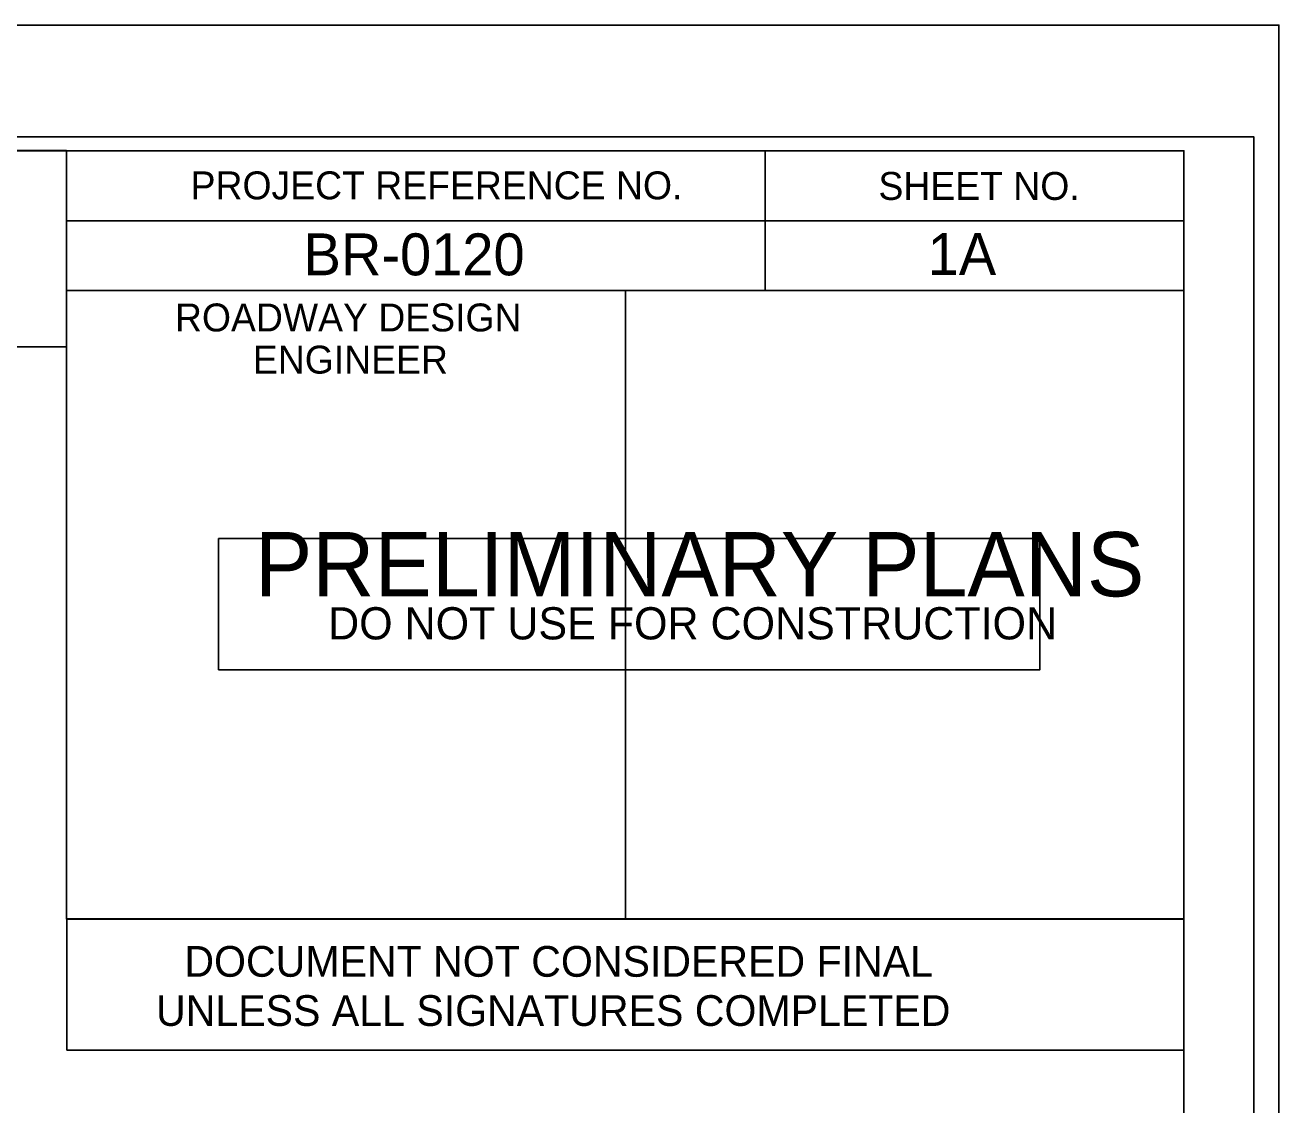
# Model space of a CAD drawing. Extents: x 2486563 to 2488026, y 371425 to 372193.
# Drawn here: x 2487379.5 to 2487469.3, y 372067.8 to 372145.1 of the extents above; entities that cross this region are included whole.
import ezdxf

# ---------------------------------------------------------------- set-up
doc = ezdxf.new("R2010")
doc.units = 0
for name, color, linetype in [('Sheet Block Title CELL', 7, 'Continuous'), ('Sheet Cutting Line CELL', 7, 'Continuous'), ('Sheet Data Field CELL', 7, 'Continuous'), ('Sheet Plan CELL', 7, 'Continuous'), ('Sheet Plot Border Inside CELL', 7, 'Continuous'), ('Sheet Plot Border Outside CELL', 7, 'Continuous'), ('Sheet Sticker Exception Certification CELL', 7, 'Continuous'), ('Sheet Sticker Preliminary CELL', 7, 'Continuous'), ('Sheet Typical CELL', 7, 'Continuous')]:
    doc.layers.add(name, color=color, linetype=linetype)

msp = doc.modelspace()

# ---------------------------------------------------------------- linework, layer by layer
at = {"layer": 'Sheet Block Title CELL'}
msp.add_lwpolyline([(2487382.471, 372126.093), (2487422.491, 372126.093), (2487422.491, 372081.093), (2487382.471, 372081.093)], close=True, dxfattribs=at)
at = {"layer": 'Sheet Cutting Line CELL'}
msp.add_line((2487469.291, 372145.113), (2486795.891, 372145.113), dxfattribs=at)
at = {"layer": 'Sheet Plan CELL'}
for p, q in [((2487432.491, 372136.093), (2487432.491, 372126.093)), ((2487382.471, 372131.093), (2487462.491, 372131.093)), ((2487382.471, 372126.093), (2487462.491, 372126.093)), ((2487382.471, 372126.093), (2487462.491, 372126.093)), ((2487422.491, 372126.093), (2487422.491, 372081.113))]:
    msp.add_line(p, q, dxfattribs=at)
for points in [[(2487462.491, 372136.113), (2486862.491, 372136.113), (2486862.491, 371716.113), (2487462.491, 371716.113)], [(2487382.471, 372136.113), (2487462.491, 372136.113), (2487462.491, 372126.093), (2487382.471, 372126.093)], [(2487422.491, 372126.093), (2487462.491, 372126.093), (2487462.491, 372081.093), (2487422.491, 372081.093)]]:
    msp.add_lwpolyline(points, close=True, dxfattribs=at)
at = {"layer": 'Sheet Plot Border Inside CELL'}
msp.add_lwpolyline([(2486801.091, 371715.113), (2487467.491, 371715.113), (2487467.491, 372137.113), (2486801.091, 372137.113)], close=True, dxfattribs=at)
at = {"layer": 'Sheet Plot Border Outside CELL'}
msp.add_lwpolyline([(2486795.891, 371707.113), (2487469.291, 371707.113), (2487469.291, 372145.113), (2486795.891, 372145.113)], close=True, dxfattribs=at)
at = {"layer": 'Sheet Sticker Exception Certification CELL'}
for p, q in [((2487382.476, 372071.698), (2487382.476, 372081.098)), ((2487382.476, 372081.098), (2487462.491, 372081.098)), ((2487462.491, 372081.093), (2487462.491, 372071.693)), ((2487462.491, 372071.698), (2487382.476, 372071.698))]:
    msp.add_line(p, q, dxfattribs=at)
at = {"layer": 'Sheet Sticker Preliminary CELL'}
msp.add_lwpolyline([(2487393.358, 372098.938), (2487393.358, 372108.338), (2487452.158, 372108.338), (2487452.158, 372098.938)], close=True, dxfattribs=at)
at = {"layer": 'Sheet Typical CELL'}
msp.add_lwpolyline([(2487382.471, 372136.14), (2487302.456, 372136.14), (2487302.456, 372122.069), (2487382.471, 372122.069)], close=True, dxfattribs=at)

# ---------------------------------------------------------------- texts
at = {"layer": 'Sheet Block Title CELL'}
for s, height, p in [('ROADWAY DESIGN', 2.00004, (2487390.231, 372123.173)), ('ENGINEER', 2, (2487395.811, 372120.153))]:
    msp.add_text(s, height=height, dxfattribs=at).set_placement(p)
at = {"layer": 'Sheet Data Field CELL'}
for s, p in [('BR-0120', (2487399.44, 372127.193)), ('1A ', (2487444.137, 372127.213))]:
    msp.add_text(s, height=3, dxfattribs=at).set_placement(p)
at = {"layer": 'Sheet Plan CELL'}
for s, height, p in [('PROJECT REFERENCE NO.', 2.00004, (2487391.351, 372132.633)), ('SHEET NO.', 2, (2487440.611, 372132.593))]:
    msp.add_text(s, height=height, dxfattribs=at).set_placement(p)
at = {"layer": 'Sheet Sticker Exception Certification CELL'}
for s, p in [('DOCUMENT NOT CONSIDERED FINAL', (2487390.904, 372076.959)), ('UNLESS ALL SIGNATURES COMPLETED', (2487388.876, 372073.439))]:
    msp.add_text(s, height=2.2, dxfattribs=at).set_placement(p)
at = {"layer": 'Sheet Sticker Preliminary CELL'}
for s, height, p in [('PRELIMINARY PLANS', 4.608, (2487395.958, 372104.198)), ('DO NOT USE FOR CONSTRUCTION', 2.304, (2487401.198, 372101.118))]:
    msp.add_text(s, height=height, dxfattribs=at).set_placement(p)

doc.saveas('drawing.dxf')
